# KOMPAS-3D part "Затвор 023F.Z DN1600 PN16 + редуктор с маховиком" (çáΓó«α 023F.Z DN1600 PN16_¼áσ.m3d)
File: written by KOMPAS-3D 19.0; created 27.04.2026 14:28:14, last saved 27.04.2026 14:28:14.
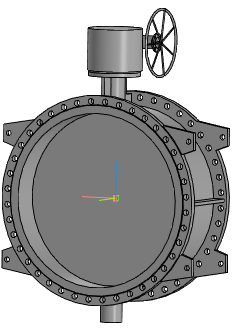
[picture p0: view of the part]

Document properties: Автор: Энергия; Полное имя файла: ..\..\Затвор 023F.Z DN200-DN1600_с маховиком\Затвор 023F.Z DN1600 PN16 + редуктор с маховиком.a3d

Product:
- Part/product: Затвор 023F.Z DN1600 PN16 + редуктор с маховиком
    Масса: 4455.08

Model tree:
1. Операция без истории:1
